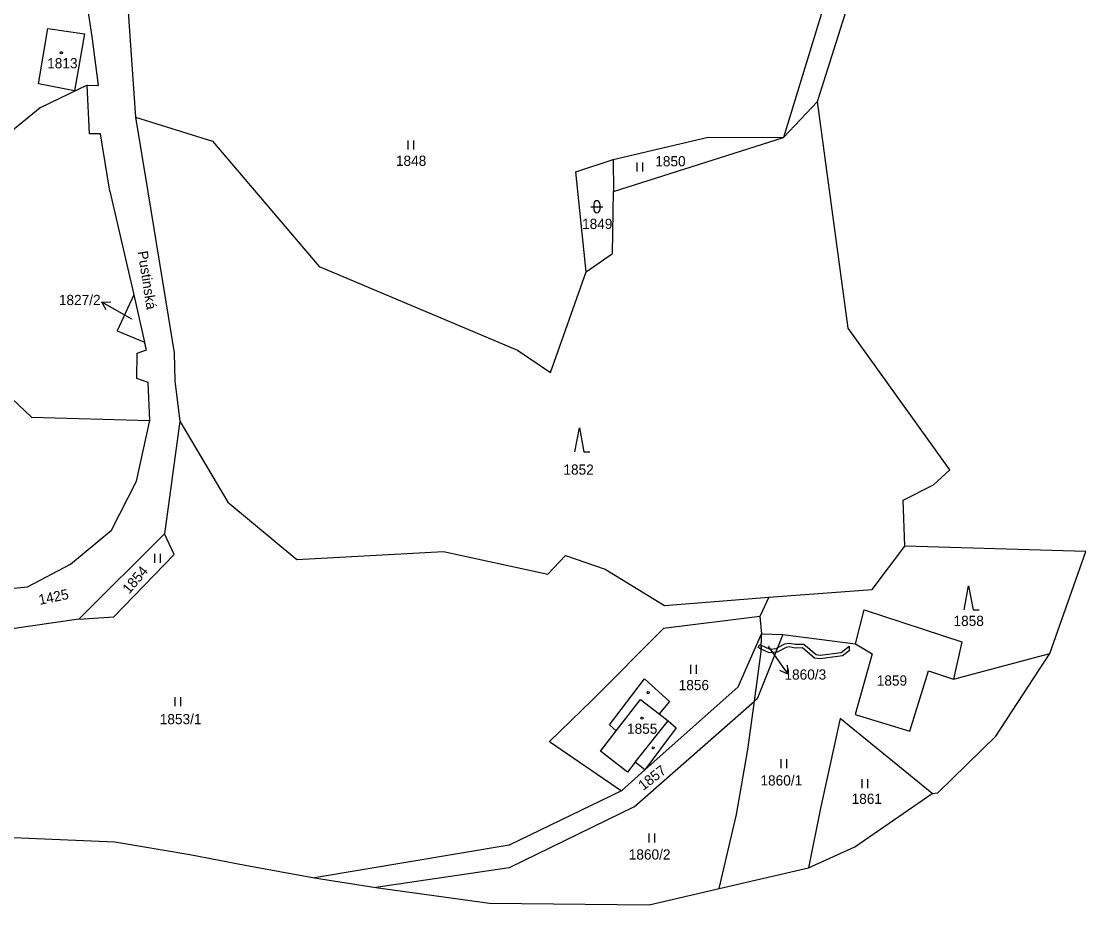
# Model space of a CAD drawing. Extents: x -670359 to -660124, y -978807 to -970072.
# Drawn here: x -668901.2 to -668723.8, y -978807.1 to -978659.9 of the extents above; entities that cross this region are included whole.
import ezdxf

# ---------------------------------------------------------------- set-up
doc = ezdxf.new("R2010")
doc.units = 0
for name, color, linetype in [('Hranice kat_území', 7, 'Continuous'), ('Hranice parcel', 7, 'Continuous'), ('Parcelní čísla', 7, 'Continuous'), ('Pop  PČ popisy', 7, 'Continuous'), ('Vnitřní kresba', 7, 'Continuous'), ('Věcná břemena k části', 7, 'Continuous'), ('Značky budov', 7, 'Continuous'), ('Značky kultur', 7, 'Continuous')]:
    doc.layers.add(name, color=color, linetype=linetype)

msp = doc.modelspace()

# ---------------------------------------------------------------- linework, layer by layer
at = {"layer": 'Hranice kat_území'}
for points in [[(-668768.5, -978673.25), (-668761.14, -978650.02)], [(-668763.39, -978711.01), (-668768.5, -978673.25)], [(-668746.43, -978734.59), (-668763.39, -978711.01)], [(-668749.12, -978737.1), (-668746.43, -978734.59)], [(-668754.21, -978739.65), (-668749.12, -978737.1)], [(-668753.94, -978747.34), (-668754.21, -978739.65)], [(-668723.78, -978748.19), (-668753.94, -978747.34)], [(-668729.78, -978765.21), (-668723.78, -978748.19)], [(-668738.74, -978778.99), (-668729.78, -978765.21)], [(-668748.42, -978788.44), (-668738.74, -978778.99)], [(-668762.25, -978797.43), (-668749.37, -978788.54)], [(-668749.37, -978788.54), (-668748.42, -978788.44)], [(-668916.93, -978795.26), (-668885.55, -978796.6)], [(-668885.55, -978796.6), (-668873.05, -978798.68)], [(-668769.99, -978800.89), (-668762.25, -978797.43)], [(-668873.05, -978798.68), (-668863.83, -978800.48)], [(-668863.83, -978800.48), (-668852.3, -978802.56)], [(-668784.84, -978804.34), (-668769.99, -978800.89)], [(-668852.3, -978802.56), (-668842.08, -978804.18)], [(-668842.08, -978804.18), (-668823.16, -978806.83)], [(-668796.51, -978807.06), (-668784.84, -978804.34)], [(-668823.16, -978806.83), (-668796.51, -978807.06)]]:
    msp.add_lwpolyline(points, dxfattribs=at)
at = {"layer": 'Hranice parcel'}
for points in [[(-668765.31, -978650.35), (-668774.13, -978679.23)], [(-668889.34, -978662.4), (-668890.13, -978657.34)], [(-668883.41, -978657.54), (-668882.13, -978675.88)], [(-668898.28, -978670.32), (-668896.76, -978661.07)], [(-668896.76, -978661.07), (-668890.61, -978661.98)], [(-668890.61, -978661.98), (-668892.3, -978671.47)], [(-668888.28, -978670.58), (-668889.34, -978662.4)], [(-668892.3, -978671.47), (-668898.28, -978670.32)], [(-668890.2, -978670.54), (-668898.03, -978674.32)], [(-668889.78, -978678.63), (-668890.2, -978670.54)], [(-668890.2, -978670.54), (-668888.28, -978670.58)], [(-668774.13, -978679.23), (-668768.5, -978673.25)], [(-668898.03, -978674.32), (-668902.9, -978678.32)], [(-668882.13, -978675.88), (-668880.1, -978688.32)], [(-668882.13, -978675.88), (-668869.31, -978679.87)], [(-668887.94, -978678.66), (-668889.78, -978678.63)], [(-668886.42, -978688.21), (-668887.94, -978678.66)], [(-668869.31, -978679.87), (-668851.5, -978700.74)], [(-668802.53, -978682.89), (-668786.7, -978679.17)], [(-668802.46, -978688.25), (-668774.13, -978679.23)], [(-668786.7, -978679.17), (-668774.13, -978679.23)], [(-668808.73, -978684.94), (-668802.53, -978682.89)], [(-668802.53, -978682.89), (-668802.46, -978688.25)], [(-668807.01, -978701.61), (-668808.73, -978684.94)], [(-668886.42, -978688.21), (-668882.43, -978705.47)], [(-668880.1, -978688.32), (-668875.68, -978715.11)], [(-668802.64, -978698.56), (-668802.46, -978688.25)], [(-668807.01, -978701.61), (-668802.64, -978698.56)], [(-668851.5, -978700.74), (-668818.45, -978714.68)], [(-668812.99, -978718.38), (-668807.01, -978701.61)], [(-668882.43, -978705.47), (-668885.16, -978711.44)], [(-668882.43, -978705.47), (-668880.61, -978713.36)], [(-668913.58, -978712.53), (-668899.48, -978725.81)], [(-668885.16, -978711.44), (-668880.61, -978713.36)], [(-668881.85, -978715.17), (-668880.32, -978714.63)], [(-668880.32, -978714.63), (-668880.61, -978713.36)], [(-668881.92, -978719.4), (-668881.85, -978715.17)], [(-668875.68, -978715.11), (-668875.6, -978719.76)], [(-668818.45, -978714.68), (-668812.99, -978718.38)], [(-668880.01, -978720.08), (-668881.92, -978719.4)], [(-668875.6, -978719.76), (-668874.76, -978726.49)], [(-668879.72, -978726.4), (-668880.01, -978720.08)], [(-668899.48, -978725.81), (-668879.72, -978726.4)], [(-668881.98, -978736.52), (-668879.72, -978726.4)], [(-668874.76, -978726.49), (-668877.32, -978745.25)], [(-668874.76, -978726.49), (-668866.75, -978739.99)], [(-668886.12, -978744.69), (-668881.98, -978736.52)], [(-668866.75, -978739.99), (-668855.23, -978749.55)], [(-668892.94, -978750.33), (-668886.12, -978744.69)], [(-668877.32, -978745.25), (-668891.55, -978759.47)], [(-668875.7, -978748.71), (-668877.32, -978745.25)], [(-668855.23, -978749.55), (-668830.79, -978748.22)], [(-668830.79, -978748.22), (-668813.41, -978751.97)], [(-668759.34, -978754.52), (-668753.94, -978747.34)], [(-668885.73, -978759.09), (-668875.7, -978748.71)], [(-668813.41, -978751.97), (-668810.47, -978748.9)], [(-668810.47, -978748.9), (-668803.87, -978751.18)], [(-668900.13, -978754.12), (-668892.94, -978750.33)], [(-668803.87, -978751.18), (-668793.97, -978757.19)], [(-668912.88, -978755.34), (-668900.13, -978754.12)], [(-668776.58, -978755.82), (-668759.34, -978754.52)], [(-668793.97, -978757.19), (-668776.58, -978755.82)], [(-668776.58, -978755.82), (-668778.07, -978759.07)], [(-668762.14, -978763.59), (-668760.68, -978757.94)], [(-668760.68, -978757.94), (-668744.45, -978763.26)], [(-668891.55, -978759.47), (-668911.96, -978762.42)], [(-668891.55, -978759.47), (-668885.73, -978759.09)], [(-668778.07, -978759.07), (-668794.16, -978761.07)], [(-668778.07, -978759.07), (-668777.8, -978761.96)], [(-668794.16, -978761.07), (-668806.03, -978773)], [(-668781.72, -978770.77), (-668777.8, -978761.96)], [(-668779, -978773.14), (-668777.88, -978764.85), (-668777.8, -978761.96)], [(-668774.28, -978762.02), (-668778.55, -978772.74), (-668779, -978773.14)], [(-668777.8, -978761.96), (-668774.28, -978762.02)], [(-668774.28, -978762.02), (-668762.14, -978763.59)], [(-668762.14, -978763.59), (-668759.37, -978765.24)], [(-668744.45, -978763.26), (-668745.84, -978769.48)], [(-668759.37, -978765.24), (-668762.19, -978775.35)], [(-668745.84, -978769.48), (-668729.78, -978765.21)], [(-668803.12, -978777.11), (-668797.3, -978769.45)], [(-668797.3, -978769.45), (-668793.12, -978773.21)], [(-668753.11, -978778.15), (-668749.99, -978768.1)], [(-668749.99, -978768.1), (-668745.84, -978769.48)], [(-668781.72, -978770.77), (-668797.24, -978784.57)], [(-668806.03, -978773), (-668813.13, -978779.89)], [(-668799.03, -978790.78), (-668779, -978773.14)], [(-668780.09, -978781.19), (-668779, -978773.14)], [(-668793.12, -978773.21), (-668794.84, -978775.26)], [(-668794.84, -978775.26), (-668793.34, -978776.4)], [(-668793.34, -978776.4), (-668792.04, -978777.62)], [(-668764.68, -978776.03), (-668768.06, -978791.25)], [(-668749.37, -978788.54), (-668764.68, -978776.03)], [(-668762.19, -978775.35), (-668753.11, -978778.15)], [(-668804.63, -978781.48), (-668802.01, -978778.09)], [(-668802.01, -978778.09), (-668803.12, -978777.11)], [(-668792.04, -978777.62), (-668797.24, -978784.57)], [(-668813.13, -978779.89), (-668801.15, -978788.1)], [(-668800.13, -978785), (-668804.63, -978781.48)], [(-668781.98, -978792.03), (-668780.09, -978781.19)], [(-668798.86, -978783.3), (-668800.13, -978785)], [(-668797.24, -978784.57), (-668798.86, -978783.3)], [(-668801.15, -978788.1), (-668797.24, -978784.57)], [(-668801.15, -978788.1), (-668819.87, -978797.13)], [(-668799.03, -978790.78), (-668819.86, -978800.89)], [(-668784.84, -978804.34), (-668781.98, -978792.03)], [(-668768.06, -978791.25), (-668769.99, -978800.89)], [(-668819.87, -978797.13), (-668852.3, -978802.56)], [(-668819.86, -978800.89), (-668842.08, -978804.18)]]:
    msp.add_lwpolyline(points, dxfattribs=at)
at = {"layer": 'Parcelní čísla'}
for p, q in [((-668887.01, -978707.96), (-668887.77, -978706.66)), ((-668882.75, -978709.52), (-668884.29, -978708.64)), ((-668776.68, -978764.03), (-668775.71, -978765.41)), ((-668773.54, -978767.18), (-668773.41, -978768.68))]:
    msp.add_line(p, q, dxfattribs=at)
for points in [[(-668884.29, -978708.64), (-668887.77, -978706.66), (-668886.27, -978706.65)], [(-668775.71, -978765.41), (-668773.41, -978768.68), (-668774.77, -978768.05)]]:
    msp.add_lwpolyline(points, dxfattribs=at)
at = {"layer": 'Vnitřní kresba'}
for points in [[(-668802.01, -978778.09), (-668797.95, -978772.9)], [(-668797.95, -978772.9), (-668794.84, -978775.26)], [(-668798.86, -978783.3), (-668793.34, -978776.4)]]:
    msp.add_lwpolyline(points, dxfattribs=at)
at = {"layer": 'Věcná břemena k části'}
for p, q in [((-668777.85, -978763.8), (-668776.43, -978764.48)), ((-668775.38, -978764.39), (-668775.18, -978764.28)), ((-668773.72, -978764.19), (-668775.2, -978764.99)), ((-668775.18, -978764.28), (-668773.92, -978763.59)), ((-668773.92, -978763.59), (-668773.18, -978763.5)), ((-668773.2, -978764.12), (-668773.72, -978764.19)), ((-668772.19, -978764.3), (-668773.2, -978764.12)), ((-668773.18, -978763.5), (-668772.15, -978763.68)), ((-668770.95, -978764.28), (-668772.19, -978764.3)), ((-668772.15, -978763.68), (-668770.73, -978763.66)), ((-668768.96, -978765.98), (-668770.95, -978764.28)), ((-668770.73, -978763.66), (-668768.7, -978765.4)), ((-668764.56, -978765.02), (-668763.2, -978763.99)), ((-668763.2, -978763.99), (-668763.2, -978764.75)), ((-668776.55, -978765.1), (-668777.87, -978764.46)), ((-668775.47, -978765.01), (-668776.55, -978765.1)), ((-668776.43, -978764.48), (-668775.38, -978764.39)), ((-668775.2, -978764.99), (-668775.47, -978765.01)), ((-668768.01, -978766.11), (-668768.96, -978765.98)), ((-668768.7, -978765.4), (-668768.01, -978765.49)), ((-668768.01, -978765.49), (-668764.56, -978765.02)), ((-668764.32, -978765.6), (-668768.01, -978766.11)), ((-668763.2, -978764.75), (-668764.32, -978765.6))]:
    msp.add_line(p, q, dxfattribs=at)
for points in [[(-668777.87, -978764.46), (-668778.35, -978764.23), (-668778.08, -978763.69), (-668777.85, -978763.8)], [(-668777.85, -978763.8), (-668777.87, -978764.46)], [(-668777.87, -978764.46), (-668777.85, -978763.8)]]:
    msp.add_lwpolyline(points, dxfattribs=at)
at = {"layer": 'Značky budov'}
for centre in [(-668894.49, -978665.12), (-668797.72, -978775.99)]:
    msp.add_circle(centre, 0.175, dxfattribs=at)
at = {"layer": 'Značky kultur'}
for p, q in [((-668836.73, -978679.77), (-668836.73, -978681.27)), ((-668835.73, -978681.27), (-668835.73, -978679.77)), ((-668798.61, -978683.4), (-668798.61, -978684.9)), ((-668797.61, -978684.9), (-668797.61, -978683.4)), ((-668806.25, -978690.78), (-668804.25, -978690.78)), ((-668805.75, -978690.28), (-668805.75, -978691.28)), ((-668804.75, -978690.28), (-668804.75, -978691.28)), ((-668878.97, -978748.6), (-668878.97, -978750.1)), ((-668877.97, -978750.1), (-668877.97, -978748.6)), ((-668789.65, -978767.12), (-668789.65, -978768.62)), ((-668788.65, -978768.62), (-668788.65, -978767.12)), ((-668875.58, -978772.47), (-668875.58, -978773.97)), ((-668874.58, -978773.97), (-668874.58, -978772.47)), ((-668774.57, -978782.84), (-668774.57, -978784.34)), ((-668773.57, -978784.34), (-668773.57, -978782.84)), ((-668761.11, -978786.16), (-668761.11, -978787.66)), ((-668760.11, -978787.66), (-668760.11, -978786.16)), ((-668796.57, -978795.18), (-668796.57, -978796.68)), ((-668795.57, -978796.68), (-668795.57, -978795.18))]:
    msp.add_line(p, q, dxfattribs=at)
for points in [[(-668808.89, -978731.63), (-668808.14, -978727.63), (-668807.39, -978731.63), (-668806.39, -978731.63)], [(-668744.06, -978757.92), (-668743.31, -978753.92), (-668742.56, -978757.92), (-668741.56, -978757.92)]]:
    msp.add_lwpolyline(points, dxfattribs=at)
for centre in [(-668894.49, -978665.12), (-668796.69, -978771.73), (-668797.72, -978775.99), (-668795.85, -978780.94)]:
    msp.add_circle(centre, 0.175, dxfattribs=at)
for centre, start, end in [((-668805.25, -978690.28), 0, 180), ((-668805.25, -978691.28), 180, 0)]:
    msp.add_arc(centre, 0.5, start, end, dxfattribs=at)

# ---------------------------------------------------------------- texts
at = {"layer": 'Parcelní čísla'}
for s, height, p in [('1813', 1.7, (-668896.85, -978667.72)), ('1848', 1.7, (-668838.73, -978683.97)), ('1850', 1.7, (-668795.51, -978684.05)), ('1849', 1.7, (-668807.71, -978694.48)), ('1827/2', 1.7, (-668894.9, -978707.16)), ('1827/2', 0.1, (-668882.75, -978709.52)), ('1852', 1.7, (-668810.82, -978735.42)), ('1858', 1.7, (-668745.81, -978760.62)), ('1860/3', 0.1, (-668776.68, -978764.03)), ('1860/3', 1.7, (-668773.98, -978769.56)), ('1856', 1.7, (-668791.61, -978771.32)), ('1859', 1.7, (-668758.6, -978770.56)), ('1853/1', 1.7, (-668878.09, -978776.99)), ('1855', 1.7, (-668800.22, -978778.59)), ('1860/1', 1.7, (-668777.98, -978787.2)), ('1861', 1.7, (-668762.79, -978790.26)), ('1860/2', 1.7, (-668799.93, -978799.54))]:
    msp.add_text(s, height=height, dxfattribs=at).set_placement(p)
for s, rotation, p in [('1854', 49.5378, (-668883.19, -978755.4)), ('1425', 11.707, (-668898.09, -978757.12)), ('1857', 37.7389, (-668797.52, -978788.12))]:
    msp.add_text(s, height=1.7, rotation=rotation, dxfattribs=at).set_placement(p)
at = {"layer": 'Pop  PČ popisy'}
msp.add_text('Pustinská', height=1.7, rotation=278.8665, dxfattribs=at).set_placement((-668881.78, -978698.27))

doc.saveas('drawing.dxf')
